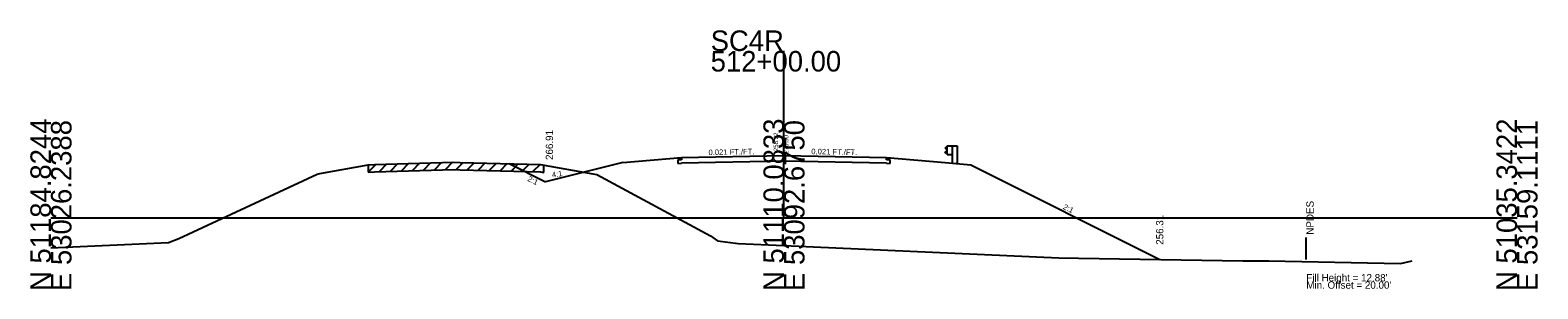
# Model space of a CAD drawing. Extents: x 7498 to 13027, y 90095 to 109625.
# Drawn here: x 8521.2 to 8726.8, y 102095.5 to 102130.7 of the extents above; entities that cross this region are included whole.
import ezdxf

# ---------------------------------------------------------------- set-up
doc = ezdxf.new("R2010")
doc.units = 0
for name, color, linetype in [('Level 10', 7, 'Continuous'), ('Level 11', 7, 'Continuous'), ('Level 12', 7, 'Continuous'), ('Level 24', 7, 'Continuous'), ('Level 32', 7, 'Continuous'), ('Level 33', 7, 'Continuous'), ('Level 50', 7, 'Continuous'), ('Level 55', 7, 'Continuous'), ('Level 59', 7, 'Continuous'), ('Level 6', 7, 'Continuous'), ('Level 60', 7, 'Continuous'), ('Level 61', 7, 'Continuous'), ('Level 63', 7, 'Continuous'), ('Level 7', 7, 'Continuous')]:
    doc.layers.add(name, color=color, linetype=linetype)

msp = doc.modelspace()

# ---------------------------------------------------------------- linework, layer by layer
at = {"layer": 'Level 11'}
for p, q in [((8609.99, 102113.07), (8609.49, 102113.05)), ((8609.49, 102113.05), (8609.49, 102112.57)), ((8609.99, 102113.37), (8609.99, 102113.07)), ((8637.99, 102113.07), (8637.99, 102113.37)), ((8638.49, 102113.05), (8637.99, 102113.07)), ((8638.49, 102112.57), (8638.49, 102113.05)), ((8609.49, 102112.57), (8609.99, 102112.59)), ((8637.99, 102112.59), (8638.49, 102112.57))]:
    msp.add_line(p, q, dxfattribs=at)
at = {"layer": 'Level 12'}
for p, q in [((8623.99, 102112.88), (8609.99, 102112.59)), ((8637.99, 102112.59), (8623.99, 102112.88))]:
    msp.add_line(p, q, dxfattribs=at)
at = {"layer": 'Level 24'}
for p, q in [((8646.26, 102114.88), (8645.99, 102114.68)), ((8646.26, 102113.78), (8646.26, 102114.95)), ((8646.26, 102114.95), (8646.93, 102114.95)), ((8646.93, 102114.95), (8646.93, 102112.6)), ((8646.93, 102114.95), (8647.6, 102114.95)), ((8647.6, 102114.95), (8647.6, 102112.54)), ((8645.99, 102114.68), (8645.99, 102114.63)), ((8645.99, 102114.63), (8646.26, 102114.43)), ((8645.99, 102114.1), (8646.26, 102114.3)), ((8645.99, 102114.05), (8645.99, 102114.1)), ((8646.26, 102113.85), (8645.99, 102114.05)), ((8646.26, 102113.78), (8646.93, 102113.78))]:
    msp.add_line(p, q, dxfattribs=at)
at = {"layer": 'Level 55'}
msp.add_line((8695.25, 102099.47), (8695.25, 102102.47), dxfattribs=at)
at = {"layer": 'Level 59'}
for p, q in [((8609.99, 102113.37), (8623.99, 102113.66)), ((8623.99, 102113.66), (8637.99, 102113.37))]:
    msp.add_line(p, q, dxfattribs=at)
at = {"layer": 'Level 6'}
for p, q in [((8601.99, 102112.7), (8609.99, 102113.37)), ((8637.99, 102113.37), (8645.99, 102112.7)), ((8645.99, 102112.7), (8649.49, 102112.35))]:
    msp.add_line(p, q, dxfattribs=at)
at = {"layer": 'Level 60'}
for p, q in [((8568.12, 102112.41), (8578.95, 102112.74)), ((8578.95, 102112.74), (8579.8, 102112.71)), ((8579.8, 102112.71), (8590.78, 102112.41)), ((8541.45, 102102.34), (8560.29, 102111.1)), ((8560.29, 102111.1), (8560.68, 102111.19)), ((8560.68, 102111.19), (8567.28, 102112.38)), ((8567.28, 102112.38), (8568.12, 102112.41)), ((8590.78, 102112.41), (8597.92, 102111.13)), ((8597.92, 102111.13), (8598.44, 102111.03)), ((8598.44, 102111.03), (8613.96, 102102.7)), ((8613.96, 102102.7), (8614.9, 102101.99)), ((8523.99, 102101.05), (8540.01, 102101.77)), ((8540.01, 102101.77), (8541.45, 102102.34)), ((8614.9, 102101.99), (8617.74, 102101.66)), ((8617.74, 102101.66), (8623.99, 102101.38)), ((8623.99, 102101.38), (8661.48, 102099.7)), ((8661.48, 102099.7), (8664.19, 102099.65)), ((8664.19, 102099.65), (8686.61, 102099.28)), ((8686.61, 102099.28), (8690.14, 102099.26)), ((8690.14, 102099.26), (8708.1, 102098.89)), ((8708.1, 102098.89), (8709.67, 102099.26))]:
    msp.add_line(p, q, dxfattribs=at)
at = {"layer": 'Level 61'}
for p, q in [((8575.78, 102112.64), (8574.75, 102111.61)), ((8577.28, 102112.69), (8576.25, 102111.66)), ((8578.78, 102112.73), (8577.75, 102111.7)), ((8580.22, 102112.7), (8579.25, 102111.73)), ((8581.72, 102112.66), (8580.75, 102111.68)), ((8568.29, 102112.42), (8567.25, 102111.38)), ((8567.25, 102112.38), (8567.25, 102111.38)), ((8567.25, 102111.38), (8567.28, 102111.38)), ((8567.28, 102111.38), (8568.12, 102111.41)), ((8568.12, 102111.41), (8578.95, 102111.74)), ((8569.78, 102112.46), (8568.75, 102111.43)), ((8571.28, 102112.51), (8570.25, 102111.48)), ((8572.78, 102112.55), (8571.75, 102111.52)), ((8574.28, 102112.6), (8573.25, 102111.57)), ((8578.95, 102111.74), (8579.8, 102111.71)), ((8579.8, 102111.71), (8590.78, 102111.41)), ((8583.22, 102112.62), (8582.25, 102111.64)), ((8584.72, 102112.57), (8583.75, 102111.6)), ((8586.22, 102112.53), (8585.25, 102111.56)), ((8587.72, 102112.49), (8586.75, 102111.52)), ((8589.22, 102112.45), (8588.25, 102111.48)), ((8590.72, 102112.41), (8589.75, 102111.44)), ((8590.78, 102111.41), (8591.21, 102111.33)), ((8591.21, 102111.33), (8591.21, 102112.33))]:
    msp.add_line(p, q, dxfattribs=at)
at = {"layer": 'Level 63'}
for p, q in [((8623.99, 102105.16), (8623.99, 102127.9)), ((8523.99, 102105.16), (8623.99, 102105.16)), ((8623.99, 102105.16), (8723.99, 102105.16))]:
    msp.add_line(p, q, dxfattribs=at)
at = {"layer": 'Level 7'}
for p, q in [((8601.99, 102112.7), (8591.45, 102110.06)), ((8586.52, 102112.53), (8591.45, 102110.06)), ((8649.49, 102112.35), (8675.25, 102099.47))]:
    msp.add_line(p, q, dxfattribs=at)

# ---------------------------------------------------------------- texts
at = {"layer": 'Level 10'}
msp.add_text('258.22', height=0.6, rotation=90, dxfattribs=at).set_placement((8623.18, 102114.24))
at = {"layer": 'Level 32'}
for s, rotation, p in [('0.021 FT./FT.', 1.1916, (8613.7, 102113.69)), ('0.021 FT./FT.', 358.8084, (8627.71, 102113.83)), ('2:1', 333.435, (8588.93, 102110.21)), ('4:1', 9.4623, (8592.39, 102110.62)), ('2:1', 333.435, (8661.98, 102106.39))]:
    msp.add_text(s, height=0.75, rotation=rotation, dxfattribs=at).set_placement(p)
at = {"layer": 'Level 33'}
for s, p in [('266.91', (8592.49, 102113.03)), ('256.31', (8675.75, 102101.47))]:
    msp.add_text(s, height=1, rotation=90, dxfattribs=at).set_placement(p)
at = {"layer": 'Level 50'}
msp.add_text(' NPDES', height=1, rotation=90, dxfattribs=at).set_placement((8696.25, 102102.47))
for s, p in [("Fill Height = 12.88' ", (8695.25, 102096.47)), ("Min. Offset = 20.00' ", (8695.25, 102095.47))]:
    msp.add_text(s, height=1, dxfattribs=at).set_placement(p)
at = {"layer": 'Level 59'}
msp.add_text(' 270.50', height=0.6, rotation=90, dxfattribs=at).set_placement((8624.59, 102113.66))
at = {"layer": 'Level 63'}
for s, p in [('SC4R', (8613.99, 102127.9)), ('512+00.00', (8613.99, 102125.1))]:
    msp.add_text(s, height=2.8, dxfattribs=at).set_placement(p)
for s, p in [('N 51184.8244', (8523.99, 102095.16)), ('E 53026.2388', (8526.79, 102095.16)), ('N 51110.0833', (8623.99, 102095.16)), ('E 53092.6750', (8626.79, 102095.16)), ('N 51035.3422', (8723.99, 102095.16)), ('E 53159.1111', (8726.79, 102095.16))]:
    msp.add_text(s, height=2.8, rotation=90, dxfattribs=at).set_placement(p)

doc.saveas('drawing.dxf')
